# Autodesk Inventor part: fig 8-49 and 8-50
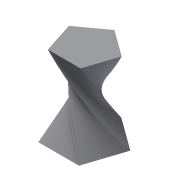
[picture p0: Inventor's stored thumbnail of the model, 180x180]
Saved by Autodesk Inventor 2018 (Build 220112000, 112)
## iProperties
Shininess: 64.0
Length Units: 11269
Angle Units: 11279
Time Units: 11290
Mass Units: 11283
Length Display Precision: 3
Angle Display Precision: 2
Compacted: True
Part Number: fig 8-49 and 8-50
Document SubType Name: Modeling
Created: 2002-12
Designer: deepak
Density: 1 g/cm^3
Material: Generic
Appearance: Default
Density: 0.0
Volumn: 0.0
Area: 0.0
PropertySet Name: Model Information
Control State: 0
Master: False
Checked Out: False
Author: deepak
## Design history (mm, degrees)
sketch "Sketch1"
  geometry: L1 (0, 21.819)-(20.751, 6.743); L2 (20.751, 6.743)-(12.825, -17.652); L3 (12.825, -17.652)-(-12.825, -17.652); L4 (-12.825, -17.652)-(-20.751, 6.743); L5 (-20.751, 6.743)-(0, 21.819); 1 further point
  constraints: 10 end point, 9 other
workplane "Work Plane1"
sketch "Sketch2"
  geometry: L1 (0, 8.24)-(7.836, 2.546); L2 (7.836, 2.546)-(4.843, -6.666); L3 (4.843, -6.666)-(-4.843, -6.666); L4 (-4.843, -6.666)-(-7.836, 2.546); L5 (-7.836, 2.546)-(0, 8.24); 1 further point
  constraints: 10 end point, 9 other
workplane "Work Plane2"
sketch "Sketch3"
  geometry: L1 (0, 17.494)-(16.637, 5.406); L2 (16.637, 5.406)-(10.283, -14.153); L3 (10.283, -14.153)-(-10.283, -14.153); L4 (-10.283, -14.153)-(-16.637, 5.406); L5 (-16.637, 5.406)-(0, 17.494); 1 further point
  constraints: 10 end point, 9 other
loft "Loft4" sketch "Sketch3" dims "d20" = 0, "d21" = 90 deg, "d22" = 0, "d23" = 90 deg, "d24" = 0, "d25" = 90 deg
body "Solid1"
other parameters: "d0" = 25, "d1" = 25
